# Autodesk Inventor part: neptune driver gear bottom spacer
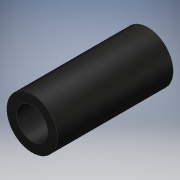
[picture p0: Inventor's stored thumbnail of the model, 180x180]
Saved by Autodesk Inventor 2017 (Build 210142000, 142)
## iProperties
Created: 2016-07
Part Number: neptune driver gear bottom spacer
Material: Generic
Document SubType Name: Modeling
Designer: Stan
Density: 1 g/cm^3
Appearance: Glossy - Black
Author: Stan
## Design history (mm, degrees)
sketch "Sketch1"
  geometry: C1 r 3.429 at (0, 0); C2 r 5.556 at (0, 0); 1 further point
  constraints: 2 centre point, 2 coincident
  dimensions: "d0" = 6.858 diameter of C1; "d1" = 11.1125 diameter of C2
extrude "Extrusion1" new body sketch "Sketch1" distance "d2" = 25.4; taper "d3" = 0 deg
body "Solid1"
